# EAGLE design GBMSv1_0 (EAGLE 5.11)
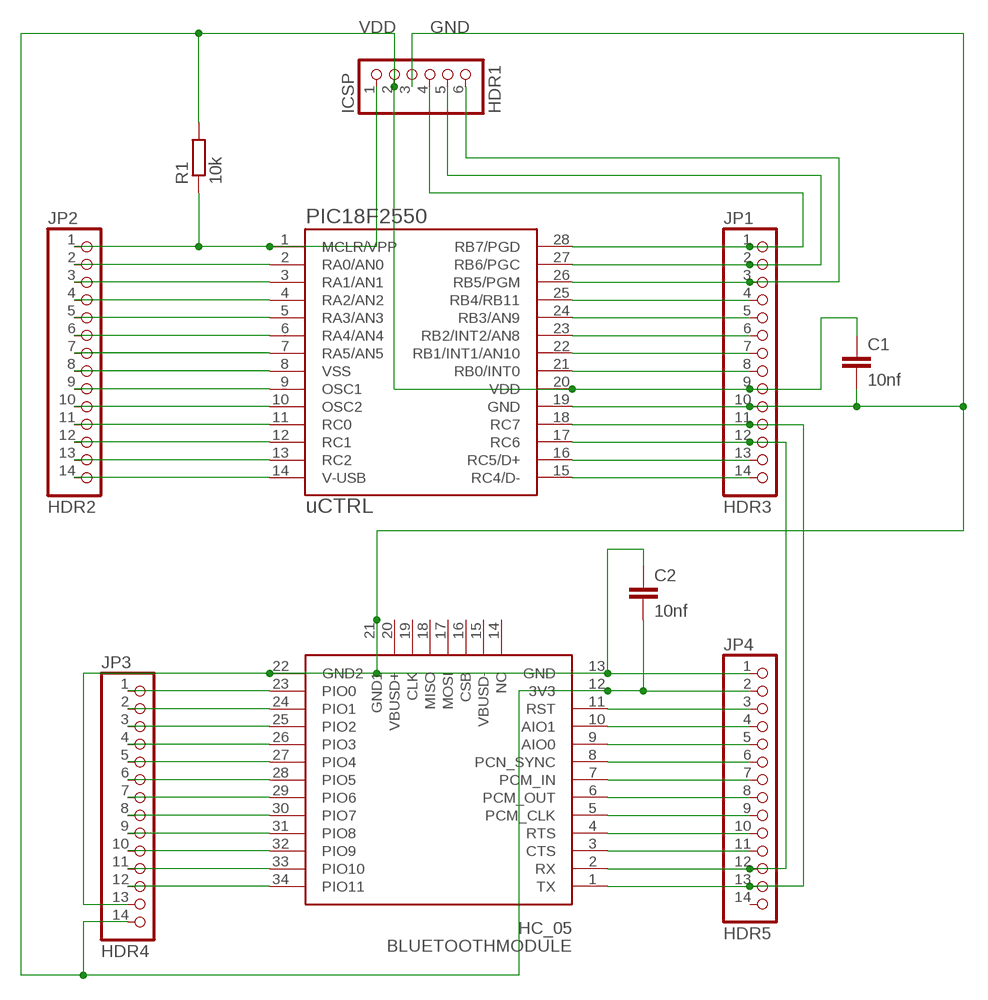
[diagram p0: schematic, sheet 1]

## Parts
BLUETOOTHMODULE  HC_05  [BLUETOOTH_SMD]
C1  10nf  C-EU025-050X050  [C025-050X050]
C2  10nf  C-EU025-050X050  [C025-050X050]
ICSP  HDR1  PINHD-1X6  [1X06]
JP1  HDR3  PINHD-1X14  [1X14]
JP2  HDR2  PINHD-1X14  [1X14]
JP3  HDR4  PINHD-1X14  [1X14]
JP4  HDR5  PINHD-1X14  [1X14]
PIC18F2550  uCTRL  PIC18F2550DIL-28  [DIL28]
R1  10k  R-EU_0207/10  [0207/10]

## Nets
GND: BLUETOOTHMODULE.13(GND) BLUETOOTHMODULE.21(GND1) BLUETOOTHMODULE.22(GND2) C1.2 C2.1 ICSP.3 JP1.10 JP3.13 JP4.1 PIC18F2550.19(GND)
N$1: BLUETOOTHMODULE.34(PIO11) JP3.12
N$2: JP2.2 PIC18F2550.2(RA0/AN0)
N$3: JP2.3 PIC18F2550.3(RA1/AN1)
N$4: JP2.4 PIC18F2550.4(RA2/AN2)
N$5: JP2.5 PIC18F2550.5(RA3/AN3)
N$6: JP2.6 PIC18F2550.6(RA4/AN4)
N$7: JP2.7 PIC18F2550.7(RA5/AN5)
N$8: JP2.8 PIC18F2550.8(VSS)
N$9: JP2.9 PIC18F2550.9(OSC1)
N$10: JP2.10 PIC18F2550.10(OSC2)
N$11: JP2.11 PIC18F2550.11(RC0)
N$12: ICSP.4 JP1.1 PIC18F2550.28(RB7/PGD)
N$13: JP2.12 PIC18F2550.12(RC1)
N$14: JP2.14 PIC18F2550.14(V-USB)
N$16: ICSP.5 JP1.2 PIC18F2550.27(RB6/PGC)
N$17: ICSP.6 JP1.3 PIC18F2550.26(RB5/PGM)
N$18: JP1.4 PIC18F2550.25(RB4/RB11)
N$19: JP1.5 PIC18F2550.24(RB3/AN9)
N$20: JP1.6 PIC18F2550.23(RB2/INT2/AN8)
N$21: JP1.7 PIC18F2550.22(RB1/INT1/AN10)
N$22: JP1.8 PIC18F2550.21(RB0/INT0)
N$24: BLUETOOTHMODULE.27(PIO4) JP3.5
N$26: BLUETOOTHMODULE.23(PIO0) JP3.1
N$27: JP1.13 PIC18F2550.16(RC5/D+)
N$28: JP1.14 PIC18F2550.15(RC4/D-)
N$29: ICSP.1 JP2.1 PIC18F2550.1(MCLR/VPP) R1.1
N$30: BLUETOOTHMODULE.24(PIO1) JP3.2
N$31: BLUETOOTHMODULE.25(PIO2) JP3.3
N$32: BLUETOOTHMODULE.26(PIO3) JP3.4
N$33: BLUETOOTHMODULE.28(PIO5) JP3.6
N$34: BLUETOOTHMODULE.29(PIO6) JP3.7
N$35: BLUETOOTHMODULE.30(PIO7) JP3.8
N$36: BLUETOOTHMODULE.31(PIO8) JP3.9
N$37: BLUETOOTHMODULE.32(PIO9) JP3.10
N$38: BLUETOOTHMODULE.33(PIO10) JP3.11
N$39: BLUETOOTHMODULE.11(RST) JP4.3
N$40: JP2.13 PIC18F2550.13(RC2)
N$41: BLUETOOTHMODULE.10(AIO1) JP4.4
N$42: BLUETOOTHMODULE.9(AIO0) JP4.5
N$43: BLUETOOTHMODULE.8(PCN_SYNC) JP4.6
N$44: BLUETOOTHMODULE.7(PCM_IN) JP4.7
N$45: BLUETOOTHMODULE.6(PCM_OUT) JP4.8
N$46: BLUETOOTHMODULE.5(PCM_CLK) JP4.9
N$47: BLUETOOTHMODULE.4(RTS) JP4.10
N$48: BLUETOOTHMODULE.3(CTS) JP4.11
N$49: BLUETOOTHMODULE.2(RX) JP1.12 JP4.12 PIC18F2550.17(RC6)
N$50: BLUETOOTHMODULE.1(TX) JP1.11 JP4.13 PIC18F2550.18(RC7)
VDD: BLUETOOTHMODULE.12(3V3) C1.1 C2.2 ICSP.2 JP1.9 JP3.14 JP4.2 PIC18F2550.20(VDD) R1.2
Unconnected: BLUETOOTHMODULE.14(NC) BLUETOOTHMODULE.15(VBUSD-) BLUETOOTHMODULE.16(CSB) BLUETOOTHMODULE.17(MOSI) BLUETOOTHMODULE.18(MISO) BLUETOOTHMODULE.19(CLK) BLUETOOTHMODULE.20(VBUSD+) JP4.14

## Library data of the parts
BLUETOOTHMODULE = SerialPortBluetooth:HC_05
C1 C2 = resistor:C-EU: CAPACITOR, European symbol
ICSP = pinhead:PINHD-1X6: PIN HEADER
JP1-JP4 = pinhead:PINHD-1X14: PIN HEADER
PIC18F2550 = pic18f2550:PIC18F2550: PIC18F2550 Richard Myrick T. Arellaga April 2010
R1 = resistor:R-EU_: RESISTOR, European symbol

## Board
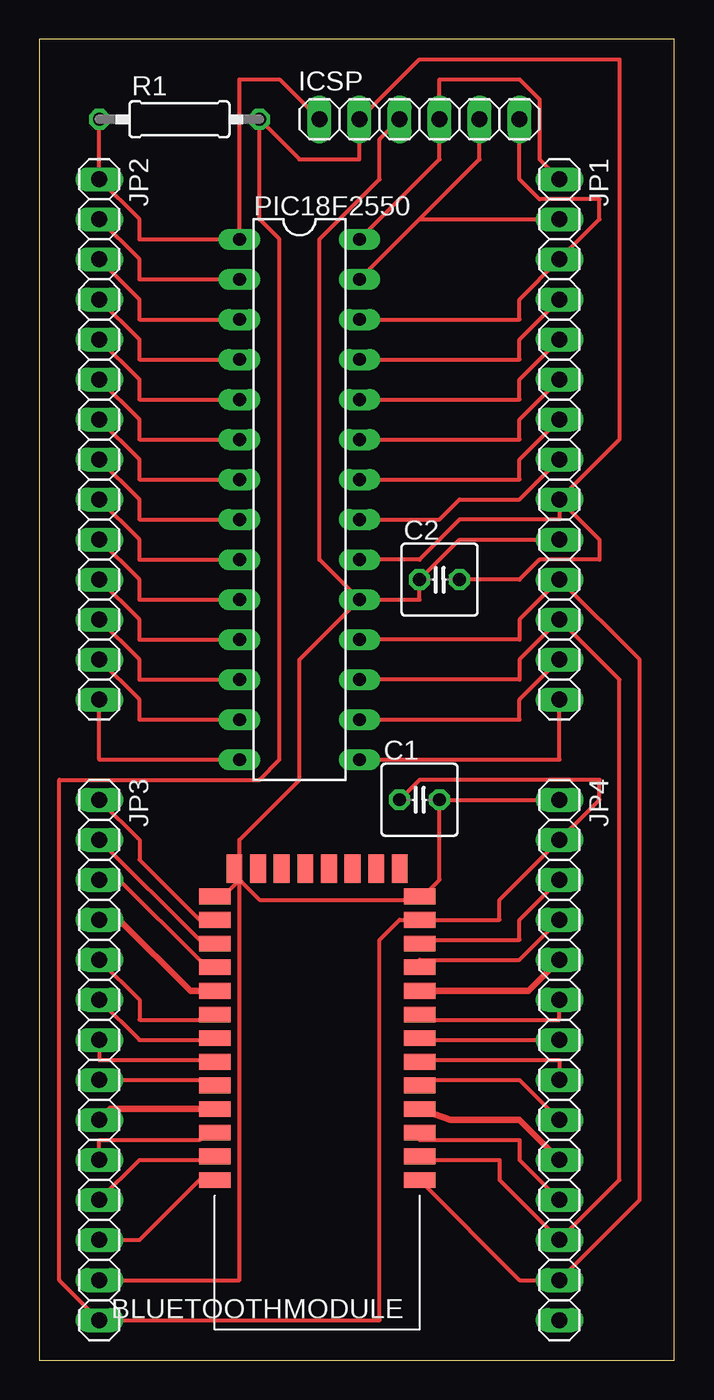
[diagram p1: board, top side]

Size 40.31 x 83.81 mm. Coordinates in mm from the lower left corner, seen from the top.
Outline: 0,0 40.31,0 40.31,83.81 0,83.81 0,0
Copper layers 1: Top 0.035mm
Design rules "default *": minimum track width 10mil, minimum drill 24mil, track to track 8mil, track to pad 8mil, pad to pad 8mil, via to via 8mil, smd to smd 8mil, copper to edge 40mil, drill to drill 8mil, minimum pad ring 10mil, minimum via ring 8mil, stop-mask expansion 4mil, vias tented up to drill 0mil, thermal gap 10mil

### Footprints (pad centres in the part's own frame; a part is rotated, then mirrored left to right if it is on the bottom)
BLUETOOTH_SMD = smd 2 x 1: 1 0,0; 2 0,-1.5; 3 0,-3; 4 0,-4.5; 5 0,-6; 6 0,-7.5; 7 0,-9; 8 0,-10.5; 9 0,-12; 10 0,-13.5; 11 0,-15; 12 0,-16.5; 13 0,-18; 22 13,-18; 23 13,-16.5; 24 13,-15; 25 13,-13.5; 26 13,-12; 27 13,-10.5; 28 13,-9; 29 13,-7.5; 30 13,-6; 31 13,-4.5; 32 13,-3; 33 13,-1.5; 34 13,0 | smd 1 x 1.8: 14 1.25,-19.75; 15 2.75,-19.75; 16 4.25,-19.75; 17 5.75,-19.75; 18 7.25,-19.75; 19 8.75,-19.75; 20 10.25,-19.75; 21 11.75,-19.75
C025-050X050 = drill 0.813 octagon: 1 -1.27,0; 2 1.27,0
1X06 = drill 1.016 long: 1 -6.35,0; 2 -3.81,0; 3 -1.27,0; 4 1.27,0; 5 3.81,0; 6 6.35,0
1X14 = drill 1.016 long: 1 -16.51,0; 2 -13.97,0; 3 -11.43,0; 4 -8.89,0; 5 -6.35,0; 6 -3.81,0; 7 -1.27,0; 8 1.27,0; 9 3.81,0; 10 6.35,0; 11 8.89,0; 12 11.43,0; 13 13.97,0; 14 16.51,0
DIL28 = drill 0.813 long: 1 -16.51,-3.81; 2 -13.97,-3.81; 3 -11.43,-3.81; 4 -8.89,-3.81; 5 -6.35,-3.81; 6 -3.81,-3.81; 7 -1.27,-3.81; 8 1.27,-3.81; 9 3.81,-3.81; 10 6.35,-3.81; 11 8.89,-3.81; 12 11.43,-3.81; 13 13.97,-3.81; 14 16.51,-3.81; 15 16.51,3.81; 16 13.97,3.81; 17 11.43,3.81; 18 8.89,3.81; 19 6.35,3.81; 20 3.81,3.81; 21 1.27,3.81; 22 -1.27,3.81; 23 -3.81,3.81; 24 -6.35,3.81; 25 -8.89,3.81; 26 -11.43,3.81; 27 -13.97,3.81; 28 -16.51,3.81
0207/10 = drill 0.813 octagon: 1 -5.08,0; 2 5.08,0

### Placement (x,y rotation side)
BLUETOOTHMODULE  24.13,11.43 180 top
C1  24.13,35.56 0 top
C2  25.4,49.53 0 top
ICSP  24.13,78.74 0 top
JP1  33.02,58.42 270 top
JP2  3.81,58.42 270 top
JP3  3.81,19.05 270 top
JP4  33.02,19.05 270 top
PIC18F2550  16.51,54.61 270 top
R1  8.89,78.74 0 top

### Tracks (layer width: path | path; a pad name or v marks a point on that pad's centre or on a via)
GND
  Top 0.254: PIC18F2550.19 24.13,48.26 C2.1 26.67,52.07 JP1.10 | ICSP.3 21.59,77.47 21.59,74.93 17.78,71.12 17.78,50.8 PIC18F2550.19 | 12.7,30.48 11.43,29.21 BLUETOOTHMODULE.22 | 24.13,29.21 25.4,30.48 C1.2 JP4.1 | 12.7,30.48 13.97,29.21 24.13,29.21 | 24.13,29.21 BLUETOOTHMODULE.13 | JP3.13 12.7,5.08 12.7,30.48 | 12.7,30.48 BLUETOOTHMODULE.21 12.7,31.75 12.7,33.02 16.51,36.83 16.51,44.45 PIC18F2550.19
N$1
  Top 0.254: JP3.12 6.35,7.62 10.16,11.43 BLUETOOTHMODULE.34
N$2
  Top 0.254: PIC18F2550.2 6.35,68.58 6.35,69.85 JP2.2
N$3
  Top 0.254: PIC18F2550.3 6.35,66.04 6.35,67.31 JP2.3
N$4
  Top 0.254: PIC18F2550.4 6.35,63.5 6.35,64.77 JP2.4
N$5
  Top 0.254: PIC18F2550.5 6.35,60.96 6.35,62.23 JP2.5
N$6
  Top 0.254: PIC18F2550.6 6.35,58.42 6.35,59.69 JP2.6
N$7
  Top 0.254: PIC18F2550.7 6.35,55.88 6.35,57.15 JP2.7
N$8
  Top 0.254: PIC18F2550.8 6.35,53.34 6.35,54.61 JP2.8
N$9
  Top 0.254: PIC18F2550.9 6.35,50.8 6.35,52.07 JP2.9
N$10
  Top 0.254: PIC18F2550.10 6.35,48.26 6.35,49.53 JP2.10
N$11
  Top 0.254: PIC18F2550.11 6.35,45.72 6.35,46.99 JP2.11
N$12
  Top 0.254: PIC18F2550.28 25.4,76.2 ICSP.4 25.4,81.28 30.48,81.28 31.75,80.01 31.75,76.2 JP1.1
N$13
  Top 0.254: PIC18F2550.12 6.35,43.18 6.35,44.45 JP2.12
N$14
  Top 0.254: PIC18F2550.14 3.81,38.1 JP2.14
N$16
  Top 0.254: 24.13,72.39 27.94,76.2 ICSP.5 | PIC18F2550.27 24.13,72.39 | 24.13,72.39 JP1.2
N$17
  Top 0.254: PIC18F2550.26 30.48,66.04 30.48,67.31 JP1.3 35.56,72.39 35.56,73.66 31.75,73.66 30.48,74.93 ICSP.6
N$18
  Top 0.254: PIC18F2550.25 30.48,63.5 30.48,64.77 JP1.4
N$19
  Top 0.254: PIC18F2550.24 30.48,60.96 30.48,62.23 JP1.5
N$20
  Top 0.254: PIC18F2550.23 30.48,58.42 30.48,59.69 JP1.6
N$21
  Top 0.254: PIC18F2550.22 30.48,55.88 30.48,57.15 JP1.7
N$22
  Top 0.254: PIC18F2550.21 25.4,53.34 26.67,54.61 30.48,54.61 JP1.8
N$24
  Top 0.254: JP3.5 6.35,22.86 6.35,21.59 10.16,21.59 BLUETOOTHMODULE.27
N$26
  Top 0.254: JP3.1 6.35,33.02 6.35,31.75 10.16,27.94 BLUETOOTHMODULE.23
N$27
  Top 0.254: PIC18F2550.16 30.48,40.64 30.48,41.91 JP1.13
N$28
  Top 0.254: PIC18F2550.15 33.02,38.1 JP1.14
N$29
  Top 0.254: R1.1 JP2.1 6.35,72.39 6.35,71.12 PIC18F2550.1 12.7,81.28 15.24,81.28 ICSP.1
N$30
  Top 0.254: JP3.2 10.16,26.67 BLUETOOTHMODULE.24
N$31
  Top 0.254: JP3.3 5.08,30.48 10.16,25.4 BLUETOOTHMODULE.25
N$32
  Top 0.406: BLUETOOTHMODULE.26 9.59,23.43 5.08,27.94 JP3.4
N$33
  Top 0.254: JP3.6 6.35,20.32 10.16,20.32 BLUETOOTHMODULE.28
N$34
  Top 0.254: JP3.7 3.81,19.05 10.16,19.05 BLUETOOTHMODULE.29
N$35
  Top 0.254: JP3.8 10.16,17.78 BLUETOOTHMODULE.30
N$36
  Top 0.406: BLUETOOTHMODULE.31 4.5,15.93 JP3.9
N$37
  Top 0.254: JP3.10 3.81,13.97 10.16,13.97 BLUETOOTHMODULE.32
N$38
  Top 0.254: JP3.11 6.35,12.7 10.16,12.7 BLUETOOTHMODULE.33
N$39
  Top 0.254: JP4.3 30.48,27.94 30.48,26.67 24.13,26.67 BLUETOOTHMODULE.11
N$40
  Top 0.254: PIC18F2550.13 6.35,40.64 6.35,41.91 JP2.13
N$41
  Top 0.254: JP4.4 30.48,25.4 24.13,25.4 BLUETOOTHMODULE.10
N$42
  Top 0.406: BLUETOOTHMODULE.9 31.05,23.43 JP4.5
N$43
  Top 0.254: JP4.6 33.02,21.59 24.13,21.59 BLUETOOTHMODULE.8
N$44
  Top 0.254: JP4.7 24.13,20.32 BLUETOOTHMODULE.7
N$45
  Top 0.254: JP4.8 33.02,19.05 24.13,19.05 BLUETOOTHMODULE.6
N$46
  Top 0.254: JP4.9 30.48,17.78 24.13,17.78 BLUETOOTHMODULE.5
N$47
  Top 0.406: JP4.10 30.48,15.24 26.09,15.24 BLUETOOTHMODULE.4
N$48
  Top 0.254: JP4.11 30.48,12.7 30.48,13.97 24.13,13.97 BLUETOOTHMODULE.3
N$49
  Top 0.254: BLUETOOTHMODULE.2 24.13,12.7 29.21,12.7 29.21,11.43 JP4.12 36.83,11.43 36.83,43.18 JP1.12 30.48,44.45 30.48,43.18 PIC18F2550.17
N$50
  Top 0.254: BLUETOOTHMODULE.1 30.48,5.08 JP4.13 38.1,10.16 38.1,44.45 JP1.11 30.48,46.99 30.48,45.72 PIC18F2550.18
VDD
  Top 0.254: PIC18F2550.20 24.13,50.8 26.67,53.34 33.02,53.34 JP1.9 | C2.2 30.48,49.53 31.75,50.8 35.56,50.8 35.56,52.07 JP1.9 | JP1.9 36.83,58.42 36.83,82.55 24.13,82.55 ICSP.2 20.32,76.2 16.51,76.2 R1.2 13.97,72.39 15.24,71.12 15.24,38.1 13.97,36.83 1.27,36.83 1.27,5.08 JP3.14 21.59,2.54 21.59,26.67 22.86,27.94 BLUETOOTHMODULE.12 | BLUETOOTHMODULE.12 29.21,27.94 29.21,29.21 JP4.2 35.56,35.56 35.56,36.83 24.13,36.83 C1.1 | BLUETOOTHMODULE.12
